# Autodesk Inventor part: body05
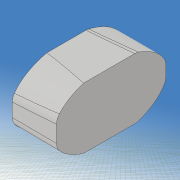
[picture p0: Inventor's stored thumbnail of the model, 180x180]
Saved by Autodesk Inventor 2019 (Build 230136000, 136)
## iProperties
Created: 2020-12
Part Number: body05
Material: 一般
Document SubType Name: Modeling
Designer: kikut
Density: 1 g/cm^3
Appearance: 既定
Mass: 87.6477 g
Surface Area: 156.124 cm^2
Volume: 87.6477 cm^3
Author: kikut
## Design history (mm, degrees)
sketch "スケッチ1"
  geometry: L1 (-100, -20)-(100, -20); L2 (100, -20)-(100, 20); L3 (100, 20)-(-100, 20); L4 (-100, 20)-(-100, -20); L5 (-100, -20)-(100, 20); L6 (100, -20)-(-100, 20); 1 further point
  constraints: 12 end point, 2 midpoint, 2 parallel, 1 horizontal, 1 perpendicular
  dimensions: "d0" = 40 distance of L3.end L1.start; "d1" = 200 distance of L2.end L3.end
extrude "押し出し1" new body sketch "スケッチ1" stored distance "d2" = 60; taper "d3" = 0 deg
sketch "スケッチ2"
  geometry: L1 (0, -60)-(0, 0) reference; L2 (200, -60)-(200, 0) reference; L3 (0, 0)-(200, 0) reference; L4 (200, -60)-(0, -60) reference; L5 (0, -26)-(0, -32); L6 (194, -10)-(194, -13); L7 (194, -13)-(174, -33); L8 (174, -33)-(200, -58); L9 (-20, 20)-(220, 20); L10 (220, 20)-(220, -100); L11 (220, -100)-(-20, -100); L12 (-20, -100)-(-20, 20); 12 further points
  constraints: 16 end point, 4 point on line, 2 parallel, 2 vertical, 1 horizontal, 1 perpendicular, 14 other
  dimensions: "d4" = 32 distance from line of point (32, -12) L1; "d5" = 50 horizontal distance of point (32, -12) point (82, -11); "d6" = 50 horizontal distance of point (132, -17) point (82, -11); "d7" = 12 distance from line of point (32, -12) L3; "d8" = 11 distance from line of point (82, -11) L3; "d10" = 17 distance from line of point (132, -17) L3; "d11" = 26 distance from line of L5.start L3; "d12" = 0 distance from line of point (200, -60) L4; "d13" = 28 distance from line of L5.end L4; "d14" = 12 distance from line of point (28, -48) L4; "d15" = 10 distance from line of point (80, -50) L4; "d16" = 16 distance from line of point (130, -44) L4; "d17" = 28 distance from line of point (28, -48) L1; "d19" = 50 horizontal distance of point (130, -44) point (80, -50); "d20" = 80 distance from line of point (80, -50) L1; "d21" = 6 distance from line of L6.start L2; "d22" = 36 distance from line of point (164, -24) L2; "d23" = 24 distance from line of point (176, -20) L2; "d24" = 10 distance from line of L6.start L3; "d25" = 20 distance from line of point (176, -20) L3; "d26" = 24 distance from line of point (164, -24) L3; "d27" = 40 distance from line of point (160, -40) L2; "d28" = 25 distance from line of point (175, -47.5) L2; "d29" = 12.5 distance from line of point (175, -47.5) L4; "d30" = 20 distance from line of L4 point (160, -40); "d31" = 3 distance of L6.start L6.end; "d32" = 33 distance from line of L7.end L3; "d33" = 26 distance from line of L7.end L2; "d34" = 2 distance of L8.end L2.start; "d35" = 120 distance of L11.end L9.start; "d36" = 240 distance of L10.end L11.end; "d37" = 20 distance between parallel lines of L1 L12; "d38" = 20 distance between parallel lines of L3 L9
extrude "押し出し2" cut sketch "スケッチ2" extent not by distance; stored distance "d39" = 0.02; taper "d40" = 0 deg
sketch "スケッチ8"
  geometry: L1 (-100, -20)-(-100, 20) reference; L2 (100, 20)-(100, -20) reference; L3 (-142.805, 0)-(142.831, 0) reference; L4 (110, 30)-(-110, 30); L5 (-110, 30)-(-110, -30); L6 (-110, -30)-(110, -30); L7 (110, -30)-(110, 30); L8 (110, 30)-(-110, -30); L9 (-110, 30)-(110, -30); L10 (-100, -2)-(-100, 2); L11 (100, -3)-(100, 3); 7 further points
  constraints: 16 end point, 4 point on line, 2 midpoint, 2 parallel, 2 perpendicular, 1 collinear, 1 horizontal, 10 other
  dimensions: "d93" = 2 vertical distance of point (0, 0) L10.end; "d94" = 2 vertical distance of L10.start point (0, 0); "d95" = 35 distance from line of point (-65, -10) L1; "d96" = 0 horizontal distance of point (-65, 10) point (-65, -10); "d97" = 10 vertical distance of point (0, 0) point (-65, -10); "d98" = 10 vertical distance of point (-65, 10) point (0, 0); "d99" = 100 distance from line of point (0, -10) L1; "d100" = 0 horizontal distance of point (0, 10) point (0, -10); "d101" = 10 distance of point (0, -10) point (0, 0); "d102" = 10 distance of point (0, 0) point (0, 10); "d103" = 160 distance from line of point (60, -4) L1; "d104" = 0 horizontal distance of point (60, 4) point (60, -4); "d105" = 4 distance from line of L3 point (60, -4); "d106" = 4 distance from line of L3 point (60, 4); "d107" = 3 distance from line of L11.start L3; "d108" = 3 distance from line of L11.end L3; "d109" = 220 distance of L5.end L6.end; "d110" = 60 distance of L4.end L5.end
extrude "押し出し6" cut sketch "スケッチ8" extent not by distance; stored distance "d111" = 10; taper "d112" = 0 deg
sketch "スケッチ9" dims "d113" = 20, "d114" = 12
  geometry: L1 (-29, -18)-(21, -18); L2 (21, -18)-(21, 22); L3 (21, 22)-(-29, 22); L4 (-29, 22)-(-29, -18); L5 (-29, -18)-(21, 22); L6 (21, -18)-(-29, 22); 2 further points; 1 other entity
  constraints: 12 end point, 2 midpoint, 2 parallel, 1 coincident, 1 horizontal, 1 perpendicular, 2 other
  dimensions: "d115" = 50 distance of L2.end L3.end; "d116" = 40 distance of L1.end L2.end
extrude "押し出し7" cut sketch "スケッチ9" distance "d117" = 150; taper "d118" = 0 deg
fillet "フィレット4" dims "d119" = 4
fillet "フィレット5" dims "d120" = 4
fillet "フィレット6" dims "d121" = 2
node "作業平面2"
sketch "スケッチ10"
  geometry: L1 (0, -41.439)-(0, 38.458) reference; L2 (141.833, 0)-(-140.631, 0) reference; L3 (82.55, 12.983)-(81.45, -4.983); A1 r 9 centre (82, 4) between (82.55, 12.983) and (81.45, -4.983); 1 further point
  constraints: 2 end point, 2 point on circle, 1 centre point
  dimensions: "d123" = 82 distance from line of L1 A1.centre; "d124" = 4 distance from line of L2 A1.centre; "d125" = 9 radius of A1; "d126" = 180 deg dimension on A1.centre L3.end L3.start; "d127" = 90 deg dimension on L3.end point (0, 0) A1.centre
revolve "回転1" sketch "スケッチ10" stored, may be unused: angle "d128" = 90 deg
mirror "ミラー1"
sketch "スケッチ11"
  geometry: L1 (25, 30)-(10, 30); L2 (10, 30)-(10, -30); L3 (10, -30)-(25, -30); L4 (25, -30)-(25, 30); L5 (0, -40.648)-(0, 34.486) reference; L6 (140.69, 0)-(-139.196, 0) reference; L7 (120, 53.792)-(-120, 53.792); L8 (-120, 53.792)-(-120, -46.208); L9 (-120, -46.208)-(120, -46.208); L10 (120, -46.208)-(120, 53.792); 1 further point
  constraints: 16 end point, 4 parallel, 2 horizontal, 2 perpendicular, 2 other
  dimensions: "d129" = 10 distance between parallel lines of L5 L2; "d130" = 15 distance of L1.start L1.end; "d131" = 60 distance of L3.end L1.start; "d132" = 100 distance of L9.end L7.start; "d133" = 240 distance of L7.start L7.end
extrude "押し出し8" cut sketch "スケッチ11" stored distance "d134" = 40; taper "d135" = 0 deg
node "ソリッド1"
other parameters: "d122" = -1
